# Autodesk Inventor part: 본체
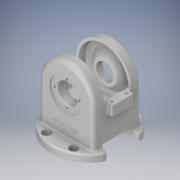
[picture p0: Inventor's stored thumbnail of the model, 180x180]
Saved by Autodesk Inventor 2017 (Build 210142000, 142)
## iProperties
Part Number: 본체
Material: 알루미늄 6061
Document SubType Name: Modeling
Designer: MRC
Density: 2.7 g/cm^3
Appearance: 알루미늄 - 평지
Mass: 1199.05 g
Surface Area: 1055.51 cm^2
Volume: 444.094 cm^3
Author: MRC
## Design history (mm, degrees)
sketch "스케치1"
  geometry: C1 r 71 at (0, 0); 1 further point
  constraints: 1 centre point, 1 coincident
  dimensions: "d0" = 142 diameter of C1
extrude "돌출1" new body sketch "스케치1" distance "d1" = 13; taper "d2" = 0 deg
sketch "스케치2"
  geometry: C1 r 51 at (0, 81); 1 further point
  constraints: 1 centre point, 1 vertical alignment
  dimensions: "d3" = 102 diameter of C1; "d4" = 81 distance of point (0, 0) C1.centre
extrude "돌출2" join sketch "스케치2" stored distance "d5" = 88; taper "d6" = 0 deg
sketch "스케치3"
  geometry: L1 (51, 81)-(51, 13); L2 (71, 13)-(-71, 13) reference; L3 (-51, 13)-(-51, 81); L4 (51, 81)-(-51, 81); L5 (-51, 13)-(51, 13); A1 r 51 centre (0, 81) between (-51, 81) and (51, 81) reference; 1 further point
  constraints: 8 end point, 2 point on circle, 1 collinear, 1 parallel, 1 perpendicular, 1 point on line, 1 tangent, 1 vertical
extrude "돌출3" join sketch "스케치3" stored distance "d10" = 88; taper "d11" = 0 deg
sketch "스케치5"
  geometry: L1 (-24, 68)-(-64, 68); L2 (-64, 68)-(-64, 48); L3 (-64, 48)-(-24, 48); L4 (-24, 48)-(-24, 68); L5 (-24, 68)-(-64, 48); L6 (-64, 68)-(-24, 48); L7 (-115, -13)-(27, -13) reference; 4 further points
  constraints: 12 end point, 4 midpoint, 2 parallel, 1 horizontal, 1 perpendicular, 1 vertical alignment
  dimensions: "d12" = 40 distance of L3.end L2.end; "d13" = 20 distance of L2.end L1.end; "d43" = 81 distance between parallel lines of L1 L7
extrude "돌출4" join sketch "스케치5" distance "d15" = 10; taper "d16" = 0 deg
sketch "스케치6"
  geometry: L1 (-71, 0)-(71, 0) reference; C1 r 30 at (0, 81); 1 further point
  constraints: 1 centre point, 1 vertical alignment
  dimensions: "d17" = 60 diameter of C1; "d18" = 81 distance from line of L1 C1.centre
extrude "돌출5" cut sketch "스케치6" distance "d19" = 2; taper "d20" = 0 deg
sketch "스케치7"
  geometry: L1 (-71, -81)-(71, -81) reference; C1 r 18.5 at (0, 0); 2 further points
  constraints: 1 centre point, 1 midpoint, 1 vertical alignment
  dimensions: "d21" = 37 diameter of C1; "d22" = 81 distance from line of L1 C1.centre
extrude "돌출6" cut sketch "스케치7" distance "d23" = 13; taper "d24" = 0 deg
sketch "스케치8"
  geometry: C1 r 16 at (0, 0); 1 further point
  constraints: 1 centre point, 1 vertical alignment
  dimensions: "d25" = 32 diameter of C1; "d26" = 81 distance of point (0, -81) C1.centre
extrude "돌출7" cut sketch "스케치8" distance "d27" = 2; taper "d28" = 0 deg
sketch "스케치9"
  geometry: C1 r 16 at (0, 0) reference; C2 r 16 at (0, 0); 1 further point
  constraints: 1 centre point, 1 coincident
  dimensions: "d29" = 32 diameter of C2
extrude "돌출8" cut sketch "스케치9" stored distance "d30" = 2; taper "d31" = 0 deg
sketch "스케치10"
  geometry: L1 (19, -28)-(0, -28); L2 (0, -28)-(0, 28); L3 (0, 28)-(19, 28); L4 (19, 28)-(19, -28); L5 (0, 71)-(0, -71) reference; 2 further points
  constraints: 8 end point, 2 midpoint, 2 parallel, 1 coincident, 1 collinear, 1 horizontal, 1 perpendicular
  dimensions: "d34" = 19 distance of L2.end L3.end; "d35" = 56 distance of L1.end L2.end
extrude "돌출9" cut sketch "스케치10" stored distance "d36" = 2; taper "d37" = 0 deg
extrude "돌출10" cut sketch "스케치10" stored distance "d38" = 2; taper "d39" = 0 deg
sketch "스케치11"
  geometry: L1 (-16, 6)-(-72, 6) reference; L2 (-115, -13)-(-72, -13) reference; L3 (-16, -13)-(27, -13) reference; L4 (-19, 119)-(-69, 119); L5 (-69, 119)-(-69, 68); L6 (-69, 68)-(-19, 68); L7 (-19, 68)-(-19, 119); L8 (-19, 119)-(-69, 68); L9 (-69, 119)-(-19, 68); 3 further points
  constraints: 12 end point, 3 midpoint, 2 parallel, 1 horizontal, 1 perpendicular, 1 vertical alignment
  dimensions: "d40" = 50 distance of L6.end L5.end; "d41" = 51 distance of L5.end L4.end; "d44" = 81 distance from line of L6.end L3
extrude "돌출11" cut sketch "스케치11" stored distance "d45" = 2; taper "d46" = 0 deg
sketch "스케치12"
  geometry: L1 (-51, 13)-(-51, 81) reference; L2 (51, 81)-(51, 13) reference; L3 (-46, 40)-(-46, 81); L4 (46, 81)-(46, 40); L5 (-46, 40)-(46, 40); L6 (65.246, 0)-(-65.246, 0) reference; A1 r 51 centre (0, 81) between (51, 81) and (-51, 81) reference; A2 r 46 centre (0, 81) between (46, 81) and (-46, 81); 1 further point
  constraints: 6 end point, 2 point on circle, 1 centre point, 1 perpendicular
  dimensions: "d47" = 5 radial gap between concentric circles of A1 A2; "d48" = 40 distance between parallel lines of L5 L6; "d49" = 5 distance between parallel lines of L1 L3; "d50" = 5 distance between parallel lines of L2 L4
extrude "돌출12" cut sketch "스케치12" stored distance "d51" = 78; taper "d52" = 0 deg
sketch "스케치13"
  geometry: L1 (81, 25)-(81, -25) reference; L2 (127, 25)-(127, 39) reference; L3 (102.5, 27)-(114.5, 39); L4 (81, 20)-(81, 25) reference; L5 (81, 39)-(40, 39) reference; L6 (62.5, 42)-(99.5, 42) reference; L7 (127, 39)-(81, 39) reference; L8 (114.5, 39)-(81, 39); L9 (81, 39)-(81, 27); L10 (81, 25)-(81, 44) reference; L11 (102.5, 27)-(81, 27); 1 further point
  constraints: 8 end point, 1 horizontal, 1 perpendicular, 1 point on line
  dimensions: "d53" = 12 distance between parallel lines of L11 L7; "d54" = 45 deg angle of L2 L3; "d55" = 33.5 distance from line of L9 L3.end
revolve "회전1" sketch "스케치13" stored, may be unused: angle "d56" = 90 deg
sketch "스케치14"
  geometry: C1 r 21.5 at (0, 0) reference; C2 r 16 at (0, 0); 1 further point
  constraints: 1 centre point, 1 coincident
  dimensions: "d57" = 32 diameter of C2
extrude "돌출13" cut sketch "스케치14" stored distance "d58" = 10; taper "d59" = 0 deg
sketch "스케치15"
  geometry: C1 r 18.5 at (0, 0) reference; 1 further point
extrude "돌출14" cut sketch "스케치15" distance "d60" = 13; taper "d61" = 0 deg
sketch "스케치16" dims "d62" = 46
  geometry: C1 r 18.5 at (0, 0) reference; C2 r 30 at (0, 0) reference; 3 further points
  constraints: 2 vertical alignment, 1 coincident, 2 other
hole "구멍1" sketch "스케치16" at (0, 23) diameter "d63" = 3.242; stored, may be unused: countersink angle "d67" = 90 deg, drill point angle "d69" = 118 deg; dims "d64" = 8, "d65" = 4, "d66" = 2, "d68" = 10
sketch "스케치17"
  geometry: L1 (-105, 7)-(3, 7); L2 (3, 7)-(3, 33); L3 (3, 33)-(-105, 33); L4 (-105, 33)-(-105, 7); L5 (-105, 7)-(3, 33); L6 (3, 7)-(-105, 33); 5 further points
  constraints: 12 end point, 4 coincident, 2 midpoint, 2 parallel, 1 horizontal, 1 perpendicular
  dimensions: "d74" = 26 distance of L1.end L2.end; "d75" = 108 distance of L1.start L1.end
hole "구멍2" sketch "스케치17" at (-105, 7), (-105, 33), (3, 7), (3, 33) diameter "d76" = 3.242; stored, may be unused: countersink angle "d80" = 90 deg, drill point angle "d82" = 118 deg; dims "d77" = 8, "d78" = 4, "d79" = 2, "d81" = 10
sketch "스케치19"
  geometry: L1 (-25, -55)-(25, -55); L2 (25, -55)-(25, 55); L3 (25, 55)-(-25, 55); L4 (-25, 55)-(-25, -55); L5 (-25, -55)-(25, 55); L6 (25, -55)-(-25, 55); 8 further points
  constraints: 12 end point, 6 coincident, 4 midpoint, 1 horizontal, 1 parallel, 1 perpendicular
  dimensions: "d83" = 50 distance of L3.end L2.end; "d84" = 110 distance of L2.end L1.end
hole "구멍3" sketch "스케치19" at (-25, -55), (25, -55), (25, 55), (-25, 55) diameter "d85" = 9; stored, may be unused: countersink angle "d89" = 90 deg, drill point angle "d91" = 0 deg; dims "d86" = 8, "d87" = 15, "d88" = 8.8, "d90" = 14
sketch "스케치20"
  geometry: C1 r 11 at (46, -39); 1 further point
  constraints: 1 centre point, 1 coincident
  dimensions: "d92" = 22 diameter of C1
extrude "돌출15" cut sketch "스케치20" stored distance "d93" = 13; taper "d94" = 0 deg
sketch "스케치21"
  geometry: C1 r 30 at (0, 0); 1 further point
  constraints: 1 centre point, 1 coincident
  dimensions: "d95" = 60 diameter of C1
extrude "돌출16" cut sketch "스케치21" distance "d96" = 22; taper "d97" = 0 deg
sketch "스케치22"
  geometry: C1 r 14 at (0, 0); 1 further point
  constraints: 1 centre point, 1 coincident
  dimensions: "d98" = 28 diameter of C1
extrude "돌출17" cut sketch "스케치22" distance "d99" = 15; taper "d100" = 0 deg
sketch "스케치23" dims "d101" = 46
  geometry: 3 further points
  constraints: 2 horizontal alignment, 1 coincident, 2 other
hole "구멍4" sketch "스케치23" at (23, 0) diameter "d102" = 3.242; stored, may be unused: countersink angle "d106" = 90 deg, drill point angle "d108" = 0 deg; dims "d103" = 8, "d104" = 15, "d105" = 8.8, "d107" = 10
sketch "스케치24"
  geometry: L1 (-65.246, 0)-(65.246, 0) reference; 3 further points
  constraints: 1 midpoint, 1 vertical alignment, 1 other
  dimensions: "d112" = 30 distance from line of L1 point (0, 30)
feature "엠보싱1" sketch "스케치24" dims "d113" = 0.5, "d114" = 0
fillet "모깎기1" dims "d115" = 8
fillet "모깎기2" dims "d116" = 3
fillet "모깎기3" dims "d117" = 3
fillet "모깎기4" dims "d118" = 3
fillet "모깎기5" dims "d119" = 3
fillet "모깎기6" dims "d120" = 3
chamfer "모따기1" distance "d121" = 1; stored, may be unused: second distance "d122" = 2, angle "d123" = 45 deg
fillet "모깎기7" dims "d124" = 0.3
fillet "모깎기8" dims "d125" = 6
node "솔리드1"
mirror "미러1"
mirror "미러2"
pattern_circular "원형 패턴1" dims angle "d71" = 360 deg
mirror "미러3"
pattern_circular "원형 패턴2" dims angle "d110" = 360 deg
node "투영된 루프1"
node "투영된 루프2"
node "투영된 루프3"
